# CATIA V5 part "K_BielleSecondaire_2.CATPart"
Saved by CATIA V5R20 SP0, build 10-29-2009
Part number: Bielle_secondaire_2
Bounding box of the stored display mesh (mm): x -415 to 15, y -20 to -5, z -189.529 to -108.628
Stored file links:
  G:\Khaled_CFAO_2011\ST2M\ST2M_GR2\jcoetard\Khaled\CAD_CATIA\K_BielleSecondaire_2.CATPart
  J:\Thinkmotion\Thinkmotion_COETARD\Maquette_catia\Maquette_catia_R20_Licence_education\jcharlescoetard.CATPRODUCT\Assemblage_Pince_Prehension_Mors_Paralleles.CATProduct
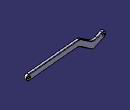
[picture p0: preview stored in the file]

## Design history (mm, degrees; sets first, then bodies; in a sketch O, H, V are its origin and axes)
Set1
  Plane1 "Plan_bielle_secondaire": linked copy from another document
  Point1: linked copy from another document
  Point2 "Point.9": linked copy from another document
Body1 (main body)
  Sketch1 on Plane1, origin (0, -5, 0), H (-1, 0, 0), V (0, 0, 1)
    construction line L1 (0, -150) -> (271.021, -123.6284)
    point P1 (0, -150)
    point P2 (271.021, -123.6284)
    line L2 (-1.4527, -135.0705) -> (269.5683, -108.6989)
    line L3 (252.5494, -140.4966) -> (1.4527, -164.9295)
    arc A1 centre (271.021, -123.6284) radius 15 from (269.5683, -108.6989) to (279.5047, -111.258) cw
    arc A2 centre (0, -150) radius 15 from (1.4527, -164.9295) to (-1.4527, -135.0705) cw
    reference projected point E1 (0, -150) from Point1
    construction line L4 (271.021, -123.6284) -> (345.2436, -174.5303)
    point P6 (271.021, -123.6284)
    point P7 (345.2436, -174.5303)
    line L5 (279.5047, -111.258) -> (328.2868, -144.7128)
    line L6 (336.76, -186.9008) -> (279.0464, -147.3208)
    construction line L7 (400, -150) -> (345.2436, -174.5303)
    point P10 (400, -150)
    point P11 (345.2436, -174.5303)
    line L8 (406.1326, -163.6891) -> (351.3762, -188.2194)
    line L9 (367.2634, -148.2292) -> (393.8674, -136.3109)
    arc A3 centre (345.2436, -174.5303) radius 15 from (351.3762, -188.2194) to (336.76, -186.9008) cw
    arc A4 centre (400, -150) radius 15 from (393.8674, -136.3109) to (406.1326, -163.6891) cw
    reference projected point E2 (400, -150) from Point2
    arc A5 centre (256.4233, -180.3086) radius 40 from (279.0464, -147.3208) to (252.5494, -140.4966) ccw
    point P17 (256.4233, -180.3086)
    arc A6 centre (350.9099, -111.725) radius 40 from (367.2634, -148.2292) to (328.2868, -144.7128) cw
    point P20 (350.9099, -111.725)
    distance L2 L3 = 30
    distance L5 L6 = 30
    distance L9 L8 = 30
    length L7 = 60
    radius A5 = 40
    distance P6 P17 = 58.5298
    radius A6 = 40
    distance P11 P20 = 63.0604
    length L4 = 90
    tangency: A1 L2, A2 L2, A1 L3, A2 L3, A3 L8, A4 L8, A3 L9, A4 L9, A5 L6, A5 L3, A1 L5, A3 L6, A6 L9, A6 L5
    coincidence: P1 E1, P6 P2, P7 P11, P10 E2
  Pad1: profile Sketch1, direction (0, -1, 0), length 15
  Sketch2 on start face of Pad1, origin (0, -5, -150), H (1, 0, 0), V (0, 0, -1)
    point P1 (0, 0)
    reference projected point E1 (0, 0) from Point1
    coincidence: E1 P1
  Hole1: placed by Sketch2, at (0, -5, -150) direction (0, -1, 0), diameter 10, depth 20
  Sketch3 on start face of Pad1, origin (-370, -5, -150), H (1, 0, 0), V (0, 0, -1)
    point P1 (-30, 0)
    reference projected point E1 (-30, 0) from Point2
    coincidence: E1 P1
  Hole2: placed by Sketch3, at (-400, -5, -150) direction (0, -1, 0), diameter 10, depth 20
  Fillet1: radius 2, on end face of Pad1; start face of Pad1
